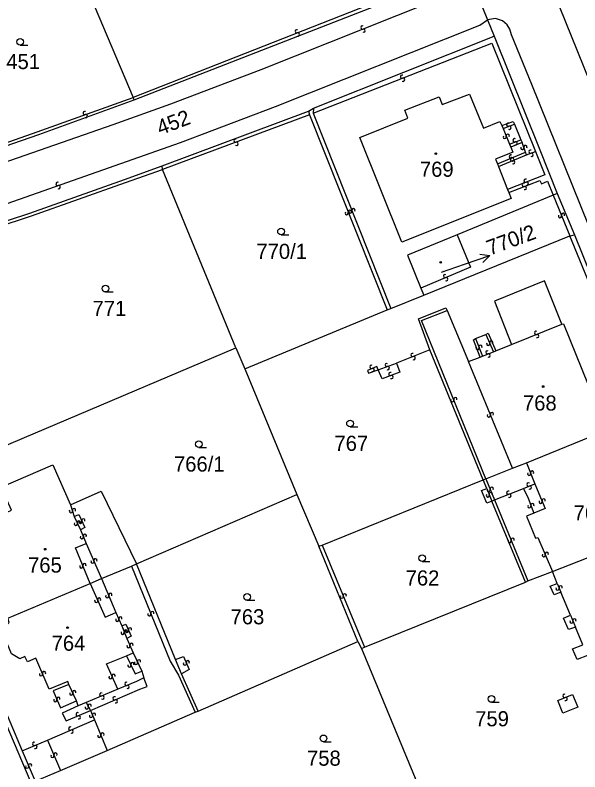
# Model space of a CAD drawing. Extents: x -600391 to -599491, y -1160176 to -1159402.
# Drawn here: x -599892 to -599828.5, y -1160127.2 to -1160042.2 of the extents above; entities that cross this region are included whole.
import ezdxf

# ---------------------------------------------------------------- set-up
doc = ezdxf.new("R2010")
doc.units = 0
for name, color, linetype in [('Level 1', 7, 'Continuous'), ('Level 13', 7, 'Continuous'), ('Level 3', 7, 'Continuous'), ('Level 4', 7, 'Continuous'), ('Level 5', 7, 'Continuous'), ('Level 57', 7, 'Continuous')]:
    doc.layers.add(name, color=color, linetype=linetype)

msp = doc.modelspace()

# ---------------------------------------------------------------- linework, layer by layer
at = {"layer": 'Level 1'}
for points in [[(-599886.45, -1160033.19), (-599878.71, -1160051.41)], [(-599841.12, -1160037.1), (-599878.65, -1160051.73)], [(-599840.4, -1160038.88), (-599838.86, -1160042.68)], [(-599838.86, -1160042.68), (-599838.11, -1160044.51)], [(-599858.41, -1160052.63), (-599838.11, -1160044.51)], [(-599838.11, -1160044.51), (-599832.97, -1160057.32), (-599831.01, -1160062.21)], [(-599878.71, -1160051.41), (-599878.65, -1160051.73)], [(-599836.43, -1160062.1), (-599836.19, -1160062.78), (-599848.48, -1160067.69), (-599853.2, -1160055.91), (-599847.79, -1160053.75), (-599848.14, -1160052.86), (-599844.29, -1160051.36), (-599843.93, -1160052.21), (-599840.86, -1160051.06), (-599839.31, -1160054.85), (-599837.46, -1160054.11), (-599837.23, -1160054.56)], [(-599878.65, -1160051.73), (-599889.35, -1160055.61), (-599898.91, -1160058.91), (-599917.43, -1160064.95)], [(-599875.46, -1160059.11), (-599858.99, -1160052.94)], [(-599858.99, -1160052.94), (-599858.41, -1160052.63)], [(-599837.23, -1160054.56), (-599835.97, -1160054.1), (-599835.82, -1160054.4)], [(-599835.82, -1160054.4), (-599835.09, -1160056.16)], [(-599834.93, -1160056.49), (-599836.21, -1160057.01)], [(-599835.09, -1160056.16), (-599834.93, -1160056.49)], [(-599836.21, -1160057.01), (-599836.01, -1160057.57), (-599837.94, -1160058.35), (-599837.73, -1160058.86)], [(-599914.24, -1160072.24), (-599890.32, -1160064.42), (-599879.7, -1160060.63), (-599875.46, -1160059.11)], [(-599875.41, -1160059.5), (-599875.46, -1160059.11)], [(-599837.73, -1160058.86), (-599837.6, -1160059.16)], [(-599837.6, -1160059.16), (-599836.6, -1160061.76)], [(-599867.15, -1160079.55), (-599875.41, -1160059.5)], [(-599836.6, -1160061.76), (-599836.43, -1160062.1)], [(-599831.47, -1160062.39), (-599842.25, -1160066.86)], [(-599831.01, -1160062.21), (-599831.47, -1160062.39)], [(-599831.01, -1160062.21), (-599829.06, -1160066.84)], [(-599842.25, -1160066.86), (-599847.85, -1160069.15), (-599846.34, -1160072.84)], [(-599846, -1160073.63), (-599829.58, -1160066.97)], [(-599829.58, -1160066.97), (-599829.06, -1160066.84)], [(-599829.06, -1160066.84), (-599820.93, -1160087.01)], [(-599830.49, -1160076.91), (-599832.45, -1160072.02), (-599838.05, -1160074.29), (-599836.13, -1160079.19)], [(-599846.34, -1160072.84), (-599846, -1160073.63)], [(-599849.73, -1160075.14), (-599846, -1160073.63)], [(-599866.16, -1160081.92), (-599850.15, -1160075.29)], [(-599850.15, -1160075.29), (-599849.73, -1160075.14)], [(-599845.35, -1160079.78), (-599846.62, -1160076.3), (-599843.52, -1160075.07), (-599843.37, -1160075.37)], [(-599843.37, -1160075.37), (-599840.99, -1160081.1)], [(-599830.49, -1160076.91), (-599830.3, -1160076.84), (-599825.45, -1160088.8)], [(-599840.2, -1160078.52), (-599839.03, -1160078.06)], [(-599839.03, -1160078.06), (-599838.76, -1160077.92), (-599837.91, -1160079.89)], [(-599839.66, -1160080.59), (-599840.42, -1160078.65), (-599840.2, -1160078.52)], [(-599903.88, -1160095.09), (-599867.15, -1160079.55)], [(-599867.15, -1160079.55), (-599866.16, -1160081.92)], [(-599839.32, -1160094.37), (-599845.35, -1160079.78)], [(-599837.91, -1160079.89), (-599836.13, -1160079.19)], [(-599840.99, -1160081.1), (-599839.66, -1160080.59)], [(-599866.16, -1160081.92), (-599860.3, -1160096.05)], [(-599834.45, -1160092.47), (-599825.45, -1160088.8)], [(-599836.05, -1160093.06), (-599834.45, -1160092.47)], [(-599892.82, -1160109.92), (-599892.99, -1160109.52), (-599893.45, -1160109.7), (-599894.41, -1160109.24), (-599895.35, -1160107), (-599895.07, -1160106.05), (-599894.52, -1160105.7), (-599894.72, -1160105.13), (-599893.81, -1160104.7), (-599895.32, -1160101.27), (-599894.41, -1160100.82), (-599893.12, -1160100.3), (-599893.91, -1160098.46), (-599892.4, -1160097.81), (-599893.55, -1160095.22), (-599887.76, -1160092.71), (-599885.76, -1160097.2)], [(-599839.02, -1160094.26), (-599836.05, -1160093.06)], [(-599857.46, -1160101.72), (-599839.32, -1160094.37)], [(-599839.32, -1160094.37), (-599839.02, -1160094.26)], [(-599838.93, -1160095.35), (-599839.32, -1160094.37)], [(-599885.76, -1160097.2), (-599882.3, -1160095.65), (-599878.35, -1160103.84)], [(-599838.34, -1160096.77), (-599838.93, -1160096.99), (-599839.53, -1160095.57), (-599838.93, -1160095.35)], [(-599878.35, -1160103.84), (-599860.3, -1160096.05)], [(-599860.3, -1160096.05), (-599857.81, -1160101.82)], [(-599834.57, -1160105.9), (-599838.34, -1160096.77)], [(-599831.52, -1160104.67), (-599820.73, -1160100.47)], [(-599857.81, -1160101.82), (-599857.46, -1160101.72)], [(-599853.44, -1160112.56), (-599857.81, -1160101.82)], [(-599882.26, -1160105.47), (-599878.89, -1160104.1)], [(-599878.89, -1160104.1), (-599878.35, -1160103.84)], [(-599873.95, -1160114.56), (-599878.35, -1160103.84)], [(-599834.29, -1160105.74), (-599831.52, -1160104.67)], [(-599831.01, -1160106.05), (-599831.52, -1160104.67)], [(-599892.82, -1160109.92), (-599883.54, -1160106.05)], [(-599883.54, -1160106.05), (-599882.26, -1160105.47)], [(-599852.68, -1160113.17), (-599834.57, -1160105.9)], [(-599834.57, -1160105.9), (-599834.29, -1160105.74)], [(-599830.58, -1160107.02), (-599831.35, -1160107.3), (-599831.79, -1160106.32), (-599831.01, -1160106.05)], [(-599829.51, -1160109.58), (-599830.58, -1160107.02)], [(-599828.94, -1160110.93), (-599829.72, -1160111.22), (-599830.31, -1160109.91), (-599829.51, -1160109.58)], [(-599828.11, -1160112.91), (-599828.94, -1160110.93)], [(-599890.2, -1160128.43), (-599897.21, -1160111.98)], [(-599871.38, -1160120.38), (-599853.44, -1160112.56)], [(-599853.44, -1160112.56), (-599853.03, -1160113.33)], [(-599827.6, -1160114.12), (-599828.77, -1160114.58), (-599829.3, -1160113.36), (-599828.11, -1160112.91)], [(-599853.03, -1160113.33), (-599852.68, -1160113.17)], [(-599853.03, -1160113.33), (-599846.33, -1160129.46)], [(-599873.26, -1160116.18), (-599873.95, -1160114.56)], [(-599871.38, -1160120.38), (-599873.26, -1160116.18)], [(-599881.62, -1160124.79), (-599871.72, -1160120.5)], [(-599871.72, -1160120.5), (-599871.38, -1160120.38)], [(-599886.89, -1160127.03), (-599881.62, -1160124.79)], [(-599889.74, -1160128.26), (-599886.89, -1160127.03)]]:
    msp.add_lwpolyline(points, dxfattribs=at)
at = {"layer": 'Level 13'}
for centre, start, end in [((-599860.307, -1160043.988), 58.59786, 291.18786), ((-599852.918, -1160043.559), 58.94252, 291.53252), ((-599852.783, -1160043.902), 239.15698, 111.25497), ((-599860.174, -1160044.332), 238.81231, 110.91031), ((-599848.466, -1160049.078), 58.71114, 290.80913), ((-599848.334, -1160049.422), 238.49668, 111.08668), ((-599884.161, -1160053.166), 57.07368, 289.17168), ((-599884.039, -1160053.514), 236.85923, 109.44923), ((-599836.517, -1160054.478), 59.17414, 291.27214), ((-599836.382, -1160054.821), 238.95969, 111.54969), ((-599836.902, -1160055.847), 148.67689, 21.26689), ((-599836.558, -1160055.714), 328.89134, 200.98934), ((-599867.203, -1160056.267), 57.46336, 290.05336), ((-599867.078, -1160056.614), 237.67782, 109.77581), ((-599835.804, -1160056.227), 58.17176, 290.26976), ((-599835.675, -1160056.572), 237.95731, 110.54731), ((-599834.575, -1160056.982), 325.90804, 198.49804), ((-599834.925, -1160057.098), 146.12249, 18.22049), ((-599834.015, -1160057.508), 58.67852, 290.77651), ((-599833.884, -1160057.852), 238.46406, 111.05406), ((-599836.207, -1160058.048), 59.36088, 291.45887), ((-599836.088, -1160058.349), 59.643, 291.741), ((-599836.072, -1160058.391), 239.14642, 111.73642), ((-599835.951, -1160058.691), 239.42855, 112.01855), ((-599887.21, -1160061.135), 56.75176, 288.84976), ((-599834.765, -1160061.248), 58.68714, 290.78514), ((-599834.556, -1160060.768), 58.39568, 290.98568), ((-599834.425, -1160061.113), 238.61013, 110.70813), ((-599887.09, -1160061.484), 236.5373, 109.1273), ((-599834.634, -1160061.592), 238.47269, 111.06269), ((-599854.681, -1160064.407), 148.86043, 21.45043), ((-599854.338, -1160064.273), 329.07488, 201.17288), ((-599854.271, -1160064.227), 148.83813, 21.42813), ((-599853.928, -1160064.093), 329.05258, 201.15058), ((-599830.349, -1160064.611), 329.7969, 201.89489), ((-599830.69, -1160064.749), 149.58244, 22.17244), ((-599843.621, -1160071.49), 59.99652, 292.58652), ((-599843.48, -1160071.831), 240.21098, 112.30898), ((-599833.378, -1160077.878), 59.38402, 291.48201), ((-599833.242, -1160078.221), 239.16956, 111.75956), ((-599838.43, -1160078.958), 331.03309, 203.13109), ((-599839.971, -1160079.569), 149.36176, 21.95176), ((-599839.629, -1160079.432), 329.57621, 201.67421), ((-599838.769, -1160079.103), 150.81863, 23.40863), ((-599847.288, -1160080.359), 59.06554, 291.65554), ((-599847.153, -1160080.702), 239.28, 111.378), ((-599838.856, -1160080.068), 58.84952, 290.94752), ((-599838.723, -1160080.412), 238.63507, 111.22507), ((-599850.182, -1160081.486), 57.44426, 289.54226), ((-599851.897, -1160081.699), 58.77306, 291.36306), ((-599851.764, -1160082.042), 238.98751, 111.08551), ((-599850.058, -1160081.833), 237.2298, 109.8198), ((-599849.776, -1160082.488), 58.40878, 290.99878), ((-599849.645, -1160082.833), 238.62324, 110.72124), ((-599842.811, -1160085.448), 149.5401, 21.6381), ((-599842.469, -1160085.311), 329.32565, 201.91565), ((-599838.691, -1160087.149), 149.81549, 21.91348), ((-599838.35, -1160087.01), 329.60103, 202.19103), ((-599834.161, -1160093.707), 148.7492, 21.3392), ((-599833.818, -1160093.574), 328.96365, 201.06165), ((-599834.229, -1160094.909), 59.70818, 291.80617), ((-599834.091, -1160095.251), 239.49372, 112.08372), ((-599838.711, -1160095.518), 149.12552, 21.71552), ((-599838.469, -1160095.991), 329.93528, 202.03327), ((-599838.368, -1160095.383), 329.33998, 201.43798), ((-599836.506, -1160095.828), 59.022, 291.12), ((-599838.81, -1160096.13), 149.72082, 22.31082), ((-599836.373, -1160096.171), 238.80755, 111.39755), ((-599832.869, -1160096.842), 150.48098, 23.07098), ((-599832.53, -1160096.699), 330.69543, 202.79343), ((-599885.364, -1160097.783), 325.80768, 197.90568), ((-599834.132, -1160097.355), 148.12679, 20.71679), ((-599833.787, -1160097.226), 328.34124, 200.43924), ((-599885.715, -1160097.897), 145.59323, 18.18323), ((-599885.147, -1160099.317), 152.17517, 24.76517), ((-599884.812, -1160099.164), 332.38963, 204.48763), ((-599884.646, -1160099.089), 152.77376, 25.36376), ((-599884.313, -1160098.932), 332.98822, 205.08621), ((-599884.48, -1160100.82), 149.85787, 22.44787), ((-599884.139, -1160100.68), 330.07232, 202.17032), ((-599836.009, -1160101.121), 329.87626, 201.97426), ((-599836.35, -1160101.26), 149.66181, 22.25181), ((-599832.17, -1160102.698), 330.84373, 202.94173), ((-599883.289, -1160103.573), 150.81048, 23.40048), ((-599882.95, -1160103.428), 331.02494, 203.12293), ((-599832.509, -1160102.843), 150.62927, 23.21927), ((-599884.531, -1160104.108), 149.51649, 21.61449), ((-599884.189, -1160103.971), 329.30204, 201.89204), ((-599830.959, -1160106.614), 151.06594, 23.65594), ((-599830.621, -1160106.467), 331.28039, 203.37839), ((-599882.531, -1160107.846), 331.50511, 203.60311), ((-599881.62, -1160107.451), 150.13929, 22.72929), ((-599881.28, -1160107.31), 330.35375, 202.45174), ((-599855.24, -1160107.51), 149.81722, 22.40722), ((-599854.899, -1160107.371), 330.03167, 202.12967), ((-599882.868, -1160107.995), 151.29066, 23.88066), ((-599876.891, -1160109.499), 149.35706, 21.94706), ((-599876.549, -1160109.362), 329.57151, 201.66951), ((-599880.49, -1160110.111), 150.26461, 22.85461), ((-599880.15, -1160109.969), 330.47906, 202.57706), ((-599829.4, -1160110.321), 150.04883, 22.63883), ((-599829.059, -1160110.18), 330.26329, 202.36128), ((-599879.07, -1160111.198), 331.02405, 203.12204), ((-599879.891, -1160111.568), 149.16956, 21.75956), ((-599879.548, -1160111.432), 329.38402, 201.48201), ((-599879.409, -1160111.343), 150.80959, 23.39959), ((-599878.901, -1160112.927), 331.16991, 203.26791), ((-599879.239, -1160113.074), 150.95546, 23.54546), ((-599878.053, -1160114.783), 332.71891, 204.81691), ((-599879.127, -1160115.258), 152.57757, 25.16757), ((-599878.793, -1160115.102), 332.79202, 204.89002), ((-599878.387, -1160114.938), 152.50445, 25.09445), ((-599872.889, -1160115.034), 151.01218, 23.60218), ((-599872.551, -1160114.887), 331.22664, 203.32464), ((-599889.07, -1160116.232), 151.04516, 23.14316), ((-599888.731, -1160116.087), 330.8307, 203.4207), ((-599880.911, -1160116.407), 330.86093, 203.45093), ((-599881.25, -1160116.553), 151.07538, 23.17338), ((-599879.47, -1160117.31), 59.89428, 292.48428), ((-599885.333, -1160118.232), 332.31365, 204.90365), ((-599879.33, -1160117.651), 240.10874, 112.20674), ((-599887.12, -1160118.987), 331.11218, 203.21017), ((-599885.668, -1160118.387), 152.52811, 24.6261), ((-599882.301, -1160118.5), 60.06405, 292.65405), ((-599882.16, -1160118.841), 240.2785, 112.3765), ((-599880.802, -1160118.94), 60.85625, 292.95425), ((-599830.189, -1160118.669), 59.94356, 292.04156), ((-599830.05, -1160119.01), 239.72911, 112.31911), ((-599887.459, -1160119.133), 150.89772, 23.48772), ((-599883.597, -1160119.783), 335.93857, 208.03657), ((-599880.657, -1160119.279), 240.6418, 113.2318), ((-599884.95, -1160120.729), 60.14092, 292.23891), ((-599883.922, -1160119.957), 155.72411, 28.31411), ((-599883.11, -1160120.779), 330.57133, 202.66932), ((-599884.81, -1160121.07), 239.92646, 112.51646), ((-599883.449, -1160120.922), 150.35687, 22.94687), ((-599885.781, -1160122.33), 60.41428, 292.51228), ((-599885.639, -1160122.67), 240.19982, 112.78982), ((-599882.51, -1160123.151), 149.99193, 22.58193), ((-599882.169, -1160123.01), 330.20639, 202.30439), ((-599889.851, -1160124.06), 60.37694, 292.47493), ((-599889.709, -1160124.4), 240.16248, 112.75248), ((-599887.79, -1160125.402), 150.33659, 22.92659), ((-599887.45, -1160125.259), 330.55104, 202.64904), ((-599890.64, -1160126.611), 150.2156, 22.8056), ((-599890.3, -1160126.469), 330.43005, 202.52805)]:
    msp.add_arc(centre, 0.184, start, end, dxfattribs=at)
at = {"layer": 'Level 3'}
for points in [[(-599846.4, -1159952.01), (-599848.08, -1159953.82), (-599859.23, -1159965.79), (-599859.58, -1159966.58), (-599859.93, -1159967.38), (-599860.05, -1159968.25), (-599859.84, -1159969.13), (-599859.47, -1159970.12), (-599859.1, -1159971.11), (-599852.79, -1159986.79), (-599837.18, -1160025.28), (-599821.6, -1160063.84), (-599805.47, -1160103.79), (-599793.95, -1160133.25), (-599793.45, -1160134.12), (-599792.68, -1160134.75), (-599791.97, -1160134.96), (-599791.42, -1160135), (-599790.84, -1160134.89)], [(-599850.01, -1160016.39), (-599841.76, -1160036.9), (-599878.71, -1160051.41)], [(-599840.4, -1160038.88), (-599841.34, -1160039.13), (-599864.36, -1160048.33), (-599874.5, -1160052.17), (-599880.99, -1160054.5), (-599902.43, -1160061.94), (-599908.17, -1160063.85), (-599916.7, -1160066.63)], [(-599914.89, -1160070.76), (-599907.55, -1160068.37), (-599900.91, -1160066.15), (-599873.39, -1160056.47), (-599862.7, -1160052.44), (-599839.71, -1160043.28), (-599838.86, -1160042.68)], [(-599799.2, -1160140.74), (-599798.6, -1160140.2), (-599798.25, -1160139.54), (-599798.08, -1160138.71), (-599798.22, -1160137.91), (-599798.5, -1160137.33), (-599811.08, -1160106.17), (-599827.45, -1160065.85), (-599833.86, -1160049.97), (-599836.15, -1160044.36), (-599836.32, -1160043.74), (-599836.62, -1160043.26), (-599837.17, -1160042.81), (-599837.94, -1160042.56), (-599838.86, -1160042.68)], [(-599858.46, -1160053.18), (-599838.34, -1160045.32), (-599833.45, -1160057.48)], [(-599899.01, -1160058.63), (-599889.49, -1160055.27), (-599878.71, -1160051.41)], [(-599858.87, -1160053.38), (-599875.41, -1160059.5)], [(-599858.99, -1160052.94), (-599858.87, -1160053.38)], [(-599858.87, -1160053.38), (-599850.15, -1160075.29)], [(-599858.41, -1160052.63), (-599858.46, -1160053.18)], [(-599858.46, -1160053.18), (-599849.73, -1160075.14)], [(-599837.23, -1160054.56), (-599837.07, -1160054.9)], [(-599837.07, -1160054.9), (-599835.82, -1160054.4)], [(-599837.07, -1160054.9), (-599836.38, -1160056.65)], [(-599836.38, -1160056.65), (-599835.09, -1160056.16)], [(-599836.38, -1160056.65), (-599836.21, -1160057.01)], [(-599834.56, -1160057.58), (-599834.93, -1160056.49)], [(-599837.73, -1160058.86), (-599834.56, -1160057.58)], [(-599833.45, -1160057.48), (-599832.38, -1160060.12), (-599836.6, -1160061.76)], [(-599834.45, -1160057.87), (-599834.56, -1160057.58)], [(-599834.45, -1160057.87), (-599833.45, -1160057.48)], [(-599837.6, -1160059.16), (-599834.45, -1160057.87)], [(-599903.88, -1160095.09), (-599913.57, -1160072.45), (-599890.16, -1160064.71), (-599879.57, -1160060.98), (-599875.41, -1160059.5)], [(-599836.43, -1160062.1), (-599832.97, -1160060.75), (-599832.76, -1160061.14), (-599832.09, -1160060.83), (-599831.47, -1160062.39)], [(-599831.47, -1160062.39), (-599829.58, -1160066.97)], [(-599842.25, -1160066.86), (-599840.76, -1160070.49), (-599846.34, -1160072.84)], [(-599821.3, -1160087.12), (-599829.58, -1160066.97)], [(-599839.02, -1160094.26), (-599846.26, -1160076.49), (-599843.37, -1160075.37)], [(-599836.13, -1160079.19), (-599830.49, -1160076.91)], [(-599839.03, -1160078.06), (-599838.18, -1160080)], [(-599840.2, -1160078.52), (-599839.4, -1160080.48)], [(-599845.35, -1160079.78), (-599849.08, -1160081.28)], [(-599839.66, -1160080.59), (-599839.4, -1160080.48)], [(-599839.4, -1160080.48), (-599838.18, -1160080)], [(-599838.18, -1160080), (-599837.91, -1160079.89)], [(-599849.08, -1160081.28), (-599848.72, -1160082.27), (-599850.7, -1160083.04), (-599851.16, -1160082.04)], [(-599851.16, -1160082.04), (-599849.08, -1160081.28)], [(-599836.05, -1160093.06), (-599840.99, -1160081.1)], [(-599851.16, -1160082.04), (-599851.3, -1160081.66), (-599852.36, -1160082.08), (-599852.22, -1160082.4), (-599851.16, -1160082.04)], [(-599834.45, -1160092.47), (-599833.52, -1160094.82)], [(-599839.02, -1160094.26), (-599838.06, -1160096.64)], [(-599834.81, -1160095.35), (-599833.52, -1160094.82)], [(-599833.52, -1160094.82), (-599833.06, -1160095.93), (-599832.34, -1160097.6), (-599833.64, -1160098.12)], [(-599838.93, -1160095.35), (-599838.34, -1160096.77)], [(-599838.06, -1160096.64), (-599834.81, -1160095.35)], [(-599834.81, -1160095.35), (-599834.28, -1160096.45), (-599833.64, -1160098.12)], [(-599838.34, -1160096.77), (-599838.06, -1160096.64)], [(-599838.06, -1160096.64), (-599834.29, -1160105.74)], [(-599885.76, -1160097.2), (-599885.33, -1160098.49)], [(-599885.33, -1160098.49), (-599884.83, -1160098.28), (-599884.13, -1160099.74), (-599884.63, -1160099.99)], [(-599885.33, -1160098.49), (-599884.63, -1160099.99)], [(-599833.64, -1160098.12), (-599834.46, -1160098.48), (-599833.43, -1160100.93), (-599833.17, -1160100.87), (-599831.52, -1160104.67)], [(-599884.63, -1160099.99), (-599883.99, -1160101.52)], [(-599883.54, -1160106.05), (-599885.18, -1160102.02), (-599883.99, -1160101.52)], [(-599883.99, -1160101.52), (-599882.26, -1160105.47)], [(-599857.46, -1160101.72), (-599852.68, -1160113.17)], [(-599878.89, -1160104.1), (-599874.54, -1160114.76), (-599873.62, -1160116.35), (-599871.72, -1160120.5)], [(-599883.54, -1160106.05), (-599881.86, -1160109.8), (-599880.64, -1160109.29)], [(-599882.26, -1160105.47), (-599880.64, -1160109.29)], [(-599831.01, -1160106.05), (-599830.58, -1160107.02)], [(-599880.64, -1160109.29), (-599880, -1160110.79)], [(-599885.93, -1160117.4), (-599886.05, -1160117.06), (-599888.14, -1160117.9), (-599889.67, -1160114.41), (-599890.6, -1160114.85), (-599890.89, -1160114.25), (-599891.46, -1160114.5), (-599892.41, -1160113.94), (-599893.3, -1160111.75), (-599893.35, -1160111.05), (-599892.67, -1160110.4), (-599892.82, -1160109.92)], [(-599829.51, -1160109.58), (-599828.94, -1160110.93)], [(-599880, -1160110.79), (-599879.54, -1160110.59), (-599878.94, -1160111.96), (-599879.43, -1160112.2)], [(-599880, -1160110.79), (-599879.43, -1160112.2)], [(-599896.79, -1160111.65), (-599891.2, -1160124.83)], [(-599879.43, -1160112.2), (-599878.72, -1160113.81)], [(-599880.45, -1160117.92), (-599881.71, -1160115.05), (-599879.44, -1160114.17)], [(-599879.44, -1160114.17), (-599878.72, -1160113.81)], [(-599879.44, -1160114.17), (-599878.48, -1160116.19), (-599877.73, -1160115.9)], [(-599878.72, -1160113.81), (-599877.73, -1160115.9)], [(-599873.95, -1160114.56), (-599873.04, -1160114.23), (-599872.39, -1160115.7), (-599873.26, -1160116.18)], [(-599877.73, -1160115.9), (-599877.49, -1160116.64)], [(-599883.51, -1160120.32), (-599877.94, -1160117.9), (-599877.12, -1160117.62), (-599877.49, -1160116.64)], [(-599877.49, -1160116.64), (-599878.35, -1160117.04), (-599880.45, -1160117.92)], [(-599885.93, -1160117.4), (-599887.71, -1160118.11), (-599886.87, -1160120.02), (-599885.08, -1160119.21)], [(-599885.08, -1160119.21), (-599885.93, -1160117.4)], [(-599880.45, -1160117.92), (-599884, -1160119.42)], [(-599830.95, -1160119.19), (-599829.29, -1160118.5), (-599828.69, -1160119.94), (-599830.36, -1160120.6), (-599830.95, -1160119.19)], [(-599884.89, -1160119.79), (-599885.08, -1160119.21)], [(-599884, -1160119.42), (-599884.89, -1160119.79)], [(-599884, -1160119.42), (-599883.51, -1160120.32)], [(-599884.89, -1160119.79), (-599886.69, -1160120.6), (-599886.25, -1160121.47), (-599883.51, -1160120.32)], [(-599883.51, -1160120.32), (-599883.06, -1160121.37)], [(-599888.35, -1160123.62), (-599883.06, -1160121.37)], [(-599883.06, -1160121.37), (-599881.62, -1160124.79)], [(-599891.2, -1160124.83), (-599888.35, -1160123.62)], [(-599888.35, -1160123.62), (-599886.89, -1160127.03)], [(-599891.2, -1160124.83), (-599889.74, -1160128.26)]]:
    msp.add_lwpolyline(points, dxfattribs=at)
at = {"layer": 'Level 5'}
for p, q in [((-599891.42, -1160045.53), (-599890.545, -1160045.53)), ((-599862.07, -1160066.86), (-599861.195, -1160066.86)), ((-599881.83, -1160073.27), (-599880.955, -1160073.27)), ((-599854.31, -1160088.43), (-599853.435, -1160088.43)), ((-599871.33, -1160090.76), (-599870.455, -1160090.76)), ((-599846.2, -1160103.56), (-599845.325, -1160103.56)), ((-599865.88, -1160107.92), (-599865.005, -1160107.92)), ((-599838.4, -1160119.38), (-599837.525, -1160119.38)), ((-599857.29, -1160123.81), (-599856.415, -1160123.81))]:
    msp.add_line(p, q, dxfattribs=at)
for centre, radius in [((-599891.42, -1160045.155), 0.375), ((-599844.66, -1160057.73), 0.09), ((-599844.66, -1160057.73), 0.0521), ((-599862.07, -1160066.485), 0.375), ((-599844.11, -1160069.94), 0.09), ((-599844.11, -1160069.94), 0.0521), ((-599881.83, -1160072.895), 0.375), ((-599832.58, -1160083.9), 0.09), ((-599832.58, -1160083.9), 0.0521), ((-599854.31, -1160088.055), 0.375), ((-599871.33, -1160090.385), 0.375), ((-599888.61, -1160102.18), 0.09), ((-599888.61, -1160102.18), 0.0521), ((-599846.2, -1160103.185), 0.375), ((-599865.88, -1160107.545), 0.375), ((-599886.09, -1160110.99), 0.09), ((-599886.09, -1160110.99), 0.0521), ((-599838.4, -1160119.005), 0.375), ((-599857.29, -1160123.435), 0.375)]:
    msp.add_circle(centre, radius, dxfattribs=at)
at = {"layer": 'Level 57'}
for p, q in [((-599841.423, -1160070.148), (-599838.582, -1160069.183)), ((-599844.02, -1160071.03), (-599841.423, -1160070.148))]:
    msp.add_line(p, q, dxfattribs=at)
msp.add_lwpolyline([(-599839.69, -1160069.031), (-599838.582, -1160069.183), (-599839.368, -1160069.978)], dxfattribs=at)

# ---------------------------------------------------------------- texts
at = {"layer": 'Level 4'}
for s, p in [('451', (-599892.979, -1160048.23)), ('769', (-599846.449, -1160060.33)), ('770/1', (-599864.845, -1160069.56)), ('771', (-599883.276, -1160075.97)), ('768', (-599834.856, -1160086.6)), ('767', (-599856.063, -1160091.13)), ('766/1', (-599874.117, -1160093.46)), ('761', (-599829.162, -1160098.94)), ('765', (-599890.53, -1160104.81)), ('762', (-599848.054, -1160106.26)), ('763', (-599867.746, -1160110.62)), ('764', (-599887.879, -1160113.59)), ('759', (-599840.23, -1160122.08)), ('758', (-599859.148, -1160126.51))]:
    msp.add_text(s, height=1.7, dxfattribs=at).set_placement(p)
for s, height, rotation, p in [('452', 1.7, 20.7, (-599875.662, -1160055.677)), ('770/2', 0.1, 20.01537, (-599844.02, -1160071.03))]:
    msp.add_text(s, height=height, rotation=rotation, dxfattribs=at).set_placement(p)
at = {"layer": 'Level 57'}
msp.add_text('770/2', height=1.7, rotation=20.01537, dxfattribs=at).set_placement((-599838.583, -1160069.183))

doc.saveas('drawing.dxf')
